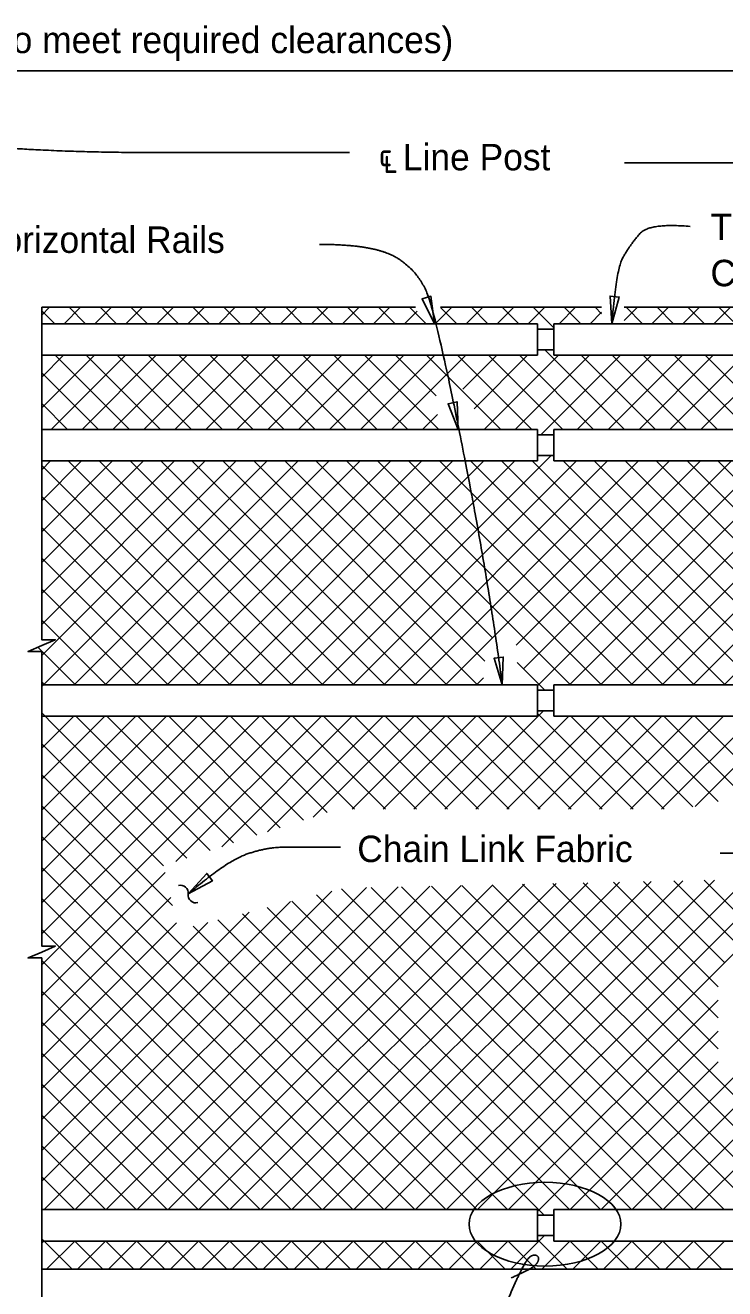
# Model space of a CAD drawing. Extents: x 110341.7 to 110413.5, y 110387.3 to 110417.8.
# Drawn here: x 110357.09 to 110362.42, y 110405.94 to 110415.57 of the extents above; entities that cross this region are included whole.
import ezdxf

# ---------------------------------------------------------------- set-up
doc = ezdxf.new("R2010")
doc.units = 0
for name, color, linetype in [('AdhocPoint_dp', 7, 'Continuous'), ('Border', 7, 'Continuous'), ('Patterning', 7, 'Continuous'), ('PlotBorder_dp', 7, 'Continuous'), ('SheetBorder_dp', 7, 'Continuous')]:
    doc.layers.add(name, color=color, linetype=linetype)

msp = doc.modelspace()

# ---------------------------------------------------------------- linework, layer by layer
at = {"layer": 'AdhocPoint_dp'}
for p, q in [((110360.9914, 110413.2966), (110357.2147, 110413.2966)), ((110360.9914, 110413.2966), (110360.9914, 110413.057)), ((110361.1164, 110413.255), (110360.9914, 110413.255)), ((110361.1164, 110413.2966), (110361.1164, 110413.057)), ((110365.0484, 110413.2966), (110361.1164, 110413.2966)), ((110360.9914, 110413.057), (110357.2147, 110413.057)), ((110361.1164, 110413.0987), (110360.9914, 110413.0987)), ((110365.0484, 110413.057), (110361.1164, 110413.057)), ((110360.9914, 110412.4912), (110357.2147, 110412.4912)), ((110360.9914, 110412.4912), (110360.9914, 110412.2516)), ((110365.0484, 110412.4912), (110361.1164, 110412.4912)), ((110361.1164, 110412.4911), (110361.1164, 110412.2516)), ((110361.1164, 110412.4495), (110360.9914, 110412.4495)), ((110361.1164, 110412.2933), (110360.9914, 110412.2933)), ((110360.9914, 110412.2516), (110357.2147, 110412.2516)), ((110365.0484, 110412.2516), (110361.1164, 110412.2516)), ((110360.9914, 110410.5466), (110357.2147, 110410.5466)), ((110360.9914, 110410.5466), (110360.9914, 110410.307)), ((110361.1164, 110410.5466), (110361.1164, 110410.307)), ((110365.0484, 110410.5466), (110361.1164, 110410.5466)), ((110361.1164, 110410.505), (110360.9914, 110410.505)), ((110360.9914, 110410.307), (110357.2147, 110410.307)), ((110361.1164, 110410.3487), (110360.9914, 110410.3487)), ((110365.0484, 110410.307), (110361.1164, 110410.307)), ((110360.9914, 110406.5466), (110357.2147, 110406.5466)), ((110360.9914, 110406.5466), (110360.9914, 110406.307)), ((110361.1164, 110406.5049), (110360.9914, 110406.5049)), ((110361.1164, 110406.5466), (110361.1164, 110406.307)), ((110365.0484, 110406.5466), (110361.1164, 110406.5466)), ((110360.9914, 110406.307), (110357.2147, 110406.307)), ((110361.1164, 110406.3487), (110360.9914, 110406.3487)), ((110365.0484, 110406.307), (110361.1164, 110406.307))]:
    msp.add_line(p, q, dxfattribs=at)
at = {"layer": 'Border'}
for points in [[(110354.5778, 110415.2246), (110356.0414, 110415.2246), (110356.0414, 110415.3279), (110356.0864, 110415.2246), (110356.1314, 110415.1213), (110356.1314, 110415.2246), (110367.5259, 110415.2246)], [(110357.2147, 110413.4227), (110357.2147, 110410.8892), (110357.3181, 110410.8892), (110357.2147, 110410.8442), (110357.1114, 110410.7992), (110357.2147, 110410.7992), (110357.2147, 110410.307)], [(110357.2147, 110410.307), (110357.2147, 110408.5545), (110357.3181, 110408.5545), (110357.2147, 110408.5095), (110357.1114, 110408.4645), (110357.2147, 110408.4645), (110357.2147, 110406.0934)], [(110357.2147, 110406.5102), (110357.2147, 110404.6594), (110357.3181, 110404.6594), (110357.2147, 110404.6144), (110357.1114, 110404.5694), (110357.2147, 110404.5694), (110357.2147, 110402.5685)]]:
    msp.add_lwpolyline(points, dxfattribs=at)
for points in [[(110360.2064, 110413.2966), (110360.1799, 110413.5062), (110360.1124, 110413.4858)], [(110361.5582, 110413.2967), (110361.6143, 110413.5003), (110361.5441, 110413.5074)], [(110360.3871, 110412.4911), (110360.3791, 110412.7022), (110360.3101, 110412.6878)], [(110360.7232, 110410.5466), (110360.7307, 110410.7577), (110360.6607, 110410.7484)], [(110358.3297, 110408.9521), (110358.5153, 110409.053), (110358.4717, 110409.1085)]]:
    msp.add_lwpolyline(points, close=True, dxfattribs=at)
for centre, start, end in [((110358.2713, 110408.9595), 352.34263, 104.06985), ((110358.3894, 110408.9436), 172.34263, 284.06985)]:
    msp.add_arc(centre, 0.0596, start, end, dxfattribs=at)
msp.add_ellipse((110361.0481, 110406.4357), major_axis=(-0.5785, 0), ratio=0.551825, dxfattribs=at)
for points in [[(110359.5594, 110414.6017), (110358.756, 110414.6017), (110357.3667, 110414.6017), (110356.1853, 110414.6963), (110355.5778, 110414.8004)], [(110361.6532, 110414.5236), (110362.0656, 110414.5236), (110363.8331, 110414.5236), (110365.0996, 110414.6466), (110365.5778, 110414.4473)], [(110362.1546, 110414.0385), (110361.8413, 110414.0669), (110361.6962, 110413.8967), (110361.5901, 110413.7126), (110361.5583, 110413.2966)], [(110359.3304, 110413.9019), (110359.7471, 110413.9019), (110360.0781, 110413.7056), (110360.2206, 110413.359), (110360.6083, 110411.4114), (110360.7232, 110410.5466)], [(110362.3836, 110409.2623), (110362.4628, 110409.2623), (110362.7363, 110409.2623), (110363.0431, 110409.3702), (110363.3333, 110409.6192)], [(110359.4911, 110409.3085), (110359.2009, 110409.3085), (110358.9273, 110409.3085), (110358.6206, 110409.2006), (110358.3304, 110408.9516)], [(110360.9877, 110405.649), (110360.7244, 110405.649), (110360.7442, 110405.8149), (110360.8614, 110406.0797), (110360.932, 110406.1998), (110360.999, 110406.1998), (110360.999, 110406.1433), (110360.9285, 110406.0868), (110360.7909, 110406.0268)]]:
    msp.add_open_spline(points, degree=2, dxfattribs=at)
at = {"layer": 'Patterning'}
for p, q in [((110357.2148, 110413.3624), (110357.2751, 110413.4227)), ((110357.2148, 110413.4227), (110360.0629, 110413.4227)), ((110357.2148, 110413.3957), (110357.3139, 110413.2966)), ((110357.3847, 110413.2966), (110357.5108, 110413.4227)), ((110357.4235, 110413.4227), (110357.5496, 110413.2966)), ((110357.6204, 110413.2966), (110357.7465, 110413.4227)), ((110357.6592, 110413.4227), (110357.7853, 110413.2966)), ((110357.8561, 110413.2966), (110357.9822, 110413.4227)), ((110357.8949, 110413.4227), (110358.021, 110413.2966)), ((110358.0918, 110413.2966), (110358.2179, 110413.4227)), ((110358.1306, 110413.4227), (110358.2567, 110413.2966)), ((110358.3275, 110413.2966), (110358.4536, 110413.4227)), ((110358.3663, 110413.4227), (110358.4924, 110413.2966)), ((110358.5632, 110413.2966), (110358.6893, 110413.4227)), ((110358.602, 110413.4227), (110358.7281, 110413.2966)), ((110358.7989, 110413.2966), (110358.925, 110413.4227)), ((110358.8377, 110413.4227), (110358.9638, 110413.2966)), ((110359.0346, 110413.2966), (110359.1607, 110413.4227)), ((110359.0734, 110413.4227), (110359.1995, 110413.2966)), ((110359.2703, 110413.2966), (110359.3964, 110413.4227)), ((110359.3091, 110413.4227), (110359.4352, 110413.2966)), ((110359.506, 110413.2966), (110359.6321, 110413.4227)), ((110359.5448, 110413.4227), (110359.6709, 110413.2966)), ((110359.7417, 110413.2966), (110359.8678, 110413.4227)), ((110359.7805, 110413.4227), (110359.9066, 110413.2966)), ((110359.9774, 110413.2966), (110360.0743, 110413.3935)), ((110360.0162, 110413.4227), (110360.1423, 110413.2966)), ((110360.2131, 110413.2966), (110360.3392, 110413.4227)), ((110360.2528, 110413.4227), (110361.4792, 110413.4227)), ((110360.2528, 110413.4218), (110360.378, 110413.2966)), ((110360.4488, 110413.2966), (110360.5749, 110413.4227)), ((110360.4876, 110413.4227), (110360.6137, 110413.2966)), ((110360.6845, 110413.2966), (110360.8106, 110413.4227)), ((110360.7233, 110413.4227), (110360.8494, 110413.2966)), ((110360.9202, 110413.2966), (110361.0463, 110413.4227)), ((110360.959, 110413.4227), (110361.1164, 110413.2654)), ((110361.1559, 110413.2966), (110361.282, 110413.4227)), ((110361.1947, 110413.4227), (110361.3208, 110413.2966)), ((110361.3916, 110413.2966), (110361.4792, 110413.3842)), ((110361.4304, 110413.4227), (110361.4792, 110413.3739)), ((110361.6525, 110413.3218), (110361.7534, 110413.4227)), ((110361.6525, 110413.4227), (110367.526, 110413.4227)), ((110361.6661, 110413.4227), (110361.7922, 110413.2966)), ((110361.863, 110413.2966), (110361.9891, 110413.4227)), ((110361.9018, 110413.4227), (110362.0279, 110413.2966)), ((110362.0987, 110413.2966), (110362.2248, 110413.4227)), ((110362.1376, 110413.4227), (110362.2636, 110413.2966)), ((110362.3345, 110413.2966), (110362.4605, 110413.4227)), ((110362.3733, 110413.4227), (110362.4993, 110413.2966)), ((110357.2148, 110412.6553), (110357.6165, 110413.057)), ((110357.2148, 110412.891), (110357.3808, 110413.057)), ((110357.2864, 110412.4912), (110357.8522, 110413.057)), ((110357.3177, 110413.057), (110357.8836, 110412.4912)), ((110357.5221, 110412.4912), (110358.0879, 110413.057)), ((110357.5534, 110413.057), (110358.1193, 110412.4912)), ((110357.7578, 110412.4912), (110358.3236, 110413.057)), ((110357.7891, 110413.057), (110358.355, 110412.4912)), ((110357.9935, 110412.4912), (110358.5593, 110413.057)), ((110358.0248, 110413.057), (110358.5907, 110412.4912)), ((110358.2292, 110412.4912), (110358.795, 110413.057)), ((110358.2605, 110413.057), (110358.8264, 110412.4912)), ((110358.4649, 110412.4912), (110359.0307, 110413.057)), ((110358.4962, 110413.057), (110359.0621, 110412.4912)), ((110358.7006, 110412.4912), (110359.2664, 110413.057)), ((110358.7319, 110413.057), (110359.2978, 110412.4912)), ((110358.9363, 110412.4912), (110359.5021, 110413.057)), ((110358.9677, 110413.057), (110359.5335, 110412.4912)), ((110359.172, 110412.4912), (110359.7378, 110413.057)), ((110359.2034, 110413.057), (110359.7692, 110412.4912)), ((110359.4077, 110412.4912), (110359.9735, 110413.057)), ((110359.4391, 110413.057), (110360.0049, 110412.4912)), ((110359.6434, 110412.4912), (110360.2093, 110413.057)), ((110359.6748, 110413.057), (110360.2406, 110412.4912)), ((110359.8791, 110412.4912), (110360.445, 110413.057)), ((110359.9105, 110413.057), (110360.22, 110412.7476)), ((110360.1462, 110413.057), (110360.712, 110412.4912)), ((110360.3819, 110413.057), (110360.9477, 110412.4912)), ((110360.4221, 110412.7985), (110360.6807, 110413.057)), ((110360.5083, 110412.649), (110360.9164, 110413.057)), ((110360.5862, 110412.4912), (110361.1521, 110413.057)), ((110360.6176, 110413.057), (110361.1834, 110412.4912)), ((110360.8219, 110412.4912), (110361.3878, 110413.057)), ((110360.8533, 110413.057), (110361.4191, 110412.4912)), ((110361.0159, 110412.4495), (110361.6235, 110413.057)), ((110361.0473, 110413.0987), (110361.6548, 110412.4912)), ((110361.2933, 110412.4912), (110361.8592, 110413.057)), ((110361.3247, 110413.057), (110361.8905, 110412.4912)), ((110361.529, 110412.4912), (110362.0949, 110413.057)), ((110361.5604, 110413.057), (110362.1262, 110412.4912)), ((110361.7647, 110412.4912), (110362.3306, 110413.057)), ((110361.7961, 110413.057), (110362.362, 110412.4912)), ((110362.0004, 110412.4912), (110362.5663, 110413.057)), ((110362.0318, 110413.057), (110362.5977, 110412.4912)), ((110362.2361, 110412.4912), (110362.802, 110413.057)), ((110362.2675, 110413.057), (110362.8334, 110412.4912)), ((110357.2148, 110412.9243), (110357.6479, 110412.4912)), ((110357.2148, 110412.6886), (110357.4122, 110412.4912)), ((110360.1148, 110412.4912), (110360.2296, 110412.606)), ((110359.3487, 110410.5466), (110361.0954, 110412.2933)), ((110357.2148, 110410.7697), (110358.6967, 110412.2516)), ((110357.2148, 110410.534), (110358.9324, 110412.2516)), ((110357.2148, 110411.0054), (110358.461, 110412.2516)), ((110357.2148, 110411.2411), (110358.2253, 110412.2516)), ((110357.2148, 110411.4768), (110357.9896, 110412.2516)), ((110357.2148, 110411.7125), (110357.7539, 110412.2516)), ((110357.2148, 110412.1839), (110357.2825, 110412.2516)), ((110357.2148, 110411.9482), (110357.5182, 110412.2516)), ((110357.2148, 110412.2172), (110358.8853, 110410.5466)), ((110357.4161, 110412.2516), (110359.121, 110410.5466)), ((110357.4631, 110410.5466), (110359.1681, 110412.2516)), ((110357.6518, 110412.2516), (110359.3567, 110410.5466)), ((110357.6988, 110410.5466), (110359.4038, 110412.2516)), ((110357.8875, 110412.2516), (110359.5925, 110410.5466)), ((110357.9345, 110410.5466), (110359.6395, 110412.2516)), ((110358.1232, 110412.2516), (110359.8282, 110410.5466)), ((110358.1702, 110410.5466), (110359.8752, 110412.2516)), ((110358.3589, 110412.2516), (110360.0639, 110410.5466)), ((110358.4059, 110410.5466), (110360.1109, 110412.2516)), ((110358.5946, 110412.2516), (110360.2996, 110410.5466)), ((110358.6416, 110410.5466), (110360.3466, 110412.2516)), ((110358.8303, 110412.2516), (110360.5353, 110410.5466)), ((110358.8773, 110410.5466), (110360.5823, 110412.2516)), ((110359.066, 110412.2516), (110360.5912, 110410.7263)), ((110359.113, 110410.5466), (110360.818, 110412.2516)), ((110359.3017, 110412.2516), (110360.6458, 110410.9075)), ((110359.5374, 110412.2516), (110361.2424, 110410.5466)), ((110359.5845, 110410.5466), (110361.2894, 110412.2516)), ((110359.7731, 110412.2516), (110361.4781, 110410.5466)), ((110359.8202, 110410.5466), (110361.5251, 110412.2516)), ((110360.0088, 110412.2516), (110361.7138, 110410.5466)), ((110360.0559, 110410.5466), (110361.7608, 110412.2516)), ((110360.2445, 110412.2516), (110361.9495, 110410.5466)), ((110360.2916, 110410.5466), (110361.9965, 110412.2516)), ((110360.4802, 110412.2516), (110362.1852, 110410.5466)), ((110360.7159, 110412.2516), (110362.4209, 110410.5466)), ((110360.8283, 110410.8477), (110362.2322, 110412.2516)), ((110360.8848, 110410.6685), (110362.4679, 110412.2516)), ((110360.9516, 110412.2516), (110362.6566, 110410.5466)), ((110360.9914, 110410.5393), (110362.7036, 110412.2516)), ((110361.1873, 110412.2516), (110362.8923, 110410.5466)), ((110361.2344, 110410.5466), (110362.9393, 110412.2516)), ((110361.423, 110412.2516), (110363.128, 110410.5466)), ((110361.4701, 110410.5466), (110363.175, 110412.2516)), ((110361.6587, 110412.2516), (110363.3637, 110410.5466)), ((110361.7058, 110410.5466), (110363.4107, 110412.2516)), ((110361.8944, 110412.2516), (110363.5994, 110410.5466)), ((110361.9415, 110410.5466), (110363.6464, 110412.2516)), ((110362.1301, 110412.2516), (110363.8351, 110410.5466)), ((110362.1772, 110410.5466), (110363.8821, 110412.2516)), ((110362.3658, 110412.2516), (110364.0708, 110410.5466)), ((110362.4129, 110410.5466), (110364.1178, 110412.2516)), ((110357.2148, 110411.9815), (110358.6496, 110410.5466)), ((110357.2148, 110411.7458), (110358.4139, 110410.5466)), ((110357.2148, 110411.5101), (110358.1782, 110410.5466)), ((110357.2148, 110411.2744), (110357.9425, 110410.5466)), ((110357.2148, 110411.0387), (110357.7068, 110410.5466)), ((110357.186, 110410.8317), (110357.4711, 110410.5466)), ((110360.8363, 110410.717), (110361.0483, 110410.505)), ((110357.2148, 110410.5673), (110357.2354, 110410.5466)), ((110360.5273, 110410.5466), (110360.5797, 110410.5991)), ((110357.2148, 110410.3316), (110357.3134, 110410.2329)), ((110357.2148, 110408.4126), (110359.1092, 110410.307)), ((110357.2148, 110408.6483), (110358.8735, 110410.307)), ((110357.2148, 110409.1197), (110358.4021, 110410.307)), ((110357.2148, 110409.3554), (110358.1664, 110410.307)), ((110357.2148, 110409.8269), (110357.695, 110410.307)), ((110357.2148, 110409.5911), (110357.9307, 110410.307)), ((110357.2148, 110410.0626), (110357.4593, 110410.307)), ((110357.2148, 110410.2983), (110357.2235, 110410.307)), ((110357.2186, 110408.8879), (110358.6378, 110410.307)), ((110357.475, 110410.307), (110358.4983, 110409.2838)), ((110357.7107, 110410.307), (110358.6762, 110409.3415)), ((110357.9464, 110410.307), (110358.8542, 110409.3993)), ((110358.1821, 110410.307), (110359.0322, 110409.457)), ((110358.2368, 110409.199), (110359.3449, 110410.307)), ((110358.328, 110410.2329), (110358.4021, 110410.307)), ((110358.4178, 110410.307), (110359.2101, 110409.5147)), ((110358.5857, 110409.3122), (110359.5806, 110410.307)), ((110358.6535, 110410.307), (110359.3881, 110409.5725)), ((110358.8892, 110410.307), (110359.5981, 110409.5981)), ((110358.9346, 110409.4253), (110359.8163, 110410.307)), ((110359.1249, 110410.307), (110359.8338, 110409.5981)), ((110359.2834, 110409.5385), (110360.052, 110410.307)), ((110359.3606, 110410.307), (110360.0695, 110409.5981)), ((110359.5788, 110409.5981), (110360.2877, 110410.307)), ((110359.5963, 110410.307), (110360.3052, 110409.5981)), ((110359.8145, 110409.5981), (110360.5234, 110410.307)), ((110359.832, 110410.307), (110360.5409, 110409.5981)), ((110360.0502, 110409.5981), (110360.7591, 110410.307)), ((110360.0677, 110410.307), (110360.7766, 110409.5981)), ((110360.2859, 110409.5981), (110361.0365, 110410.3487)), ((110360.3034, 110410.307), (110361.0123, 110409.5981)), ((110360.5216, 110409.5981), (110361.2305, 110410.307)), ((110360.5391, 110410.307), (110361.248, 110409.5981)), ((110360.7573, 110409.5981), (110361.4662, 110410.307)), ((110360.7748, 110410.307), (110361.4837, 110409.5981)), ((110360.9914, 110410.3262), (110361.7194, 110409.5981)), ((110360.993, 110409.5981), (110361.7019, 110410.307)), ((110361.2287, 110409.5981), (110361.9376, 110410.307)), ((110361.2462, 110410.307), (110361.9552, 110409.5981)), ((110361.4644, 110409.5981), (110362.1733, 110410.307)), ((110361.4819, 110410.307), (110362.1735, 110409.6155)), ((110361.7001, 110409.5981), (110362.409, 110410.307)), ((110361.7177, 110410.307), (110362.368, 110409.6567)), ((110361.9358, 110409.5981), (110362.6447, 110410.307)), ((110361.9534, 110410.307), (110362.5625, 110409.6979)), ((110362.1891, 110410.307), (110362.7571, 110409.739)), ((110362.1929, 110409.6196), (110362.8804, 110410.307)), ((110357.3134, 110410.2329), (110358.3203, 110409.2261)), ((110357.2148, 110410.0959), (110358.143, 110409.1677)), ((110357.2148, 110409.8602), (110358.2113, 110408.8636)), ((110357.2148, 110409.6245), (110360.2926, 110406.5466)), ((110357.2148, 110409.3888), (110360.0569, 110406.5466)), ((110360.5342, 110406.5466), (110363.2565, 110409.269)), ((110357.2148, 110409.1531), (110359.8212, 110406.5466)), ((110357.2148, 110408.1769), (110358.1545, 110409.1166)), ((110357.47, 110406.5466), (110359.9291, 110409.0057)), ((110357.7057, 110406.5466), (110360.1701, 110409.0109)), ((110357.9415, 110406.5466), (110360.411, 110409.0162)), ((110358.1772, 110406.5466), (110360.652, 110409.0214)), ((110358.4129, 110406.5466), (110360.893, 110409.0267)), ((110358.6486, 110406.5466), (110361.1339, 110409.032)), ((110358.8843, 110406.5466), (110361.3749, 110409.0372)), ((110359.12, 110406.5466), (110361.6159, 110409.0425)), ((110359.3557, 110406.5466), (110361.8568, 110409.0478)), ((110359.5914, 110406.5466), (110362.0978, 110409.053)), ((110359.8271, 110406.5466), (110362.3387, 110409.0583)), ((110359.9544, 110409.0062), (110362.414, 110406.5466)), ((110360.0628, 110406.5466), (110362.5797, 110409.0635)), ((110360.185, 110409.0112), (110362.6497, 110406.5466)), ((110360.2985, 110406.5466), (110362.8207, 110409.0688)), ((110360.4157, 110409.0163), (110362.8854, 110406.5466)), ((110360.6464, 110409.0213), (110363.1211, 110406.5466)), ((110360.877, 110409.0264), (110363.3568, 110406.5466)), ((110361.1077, 110409.0314), (110362.3667, 110407.7724)), ((110361.3383, 110409.0364), (110362.3667, 110408.0081)), ((110361.569, 110409.0415), (110362.3667, 110408.2438)), ((110361.7997, 110409.0465), (110362.4169, 110408.4293)), ((110362.0303, 110409.0515), (110362.6104, 110408.4715)), ((110362.261, 110409.0566), (110362.8461, 110408.4715)), ((110357.2147, 110406.7627), (110359.4258, 110408.9738)), ((110357.2148, 110407.9412), (110358.1977, 110408.9242)), ((110357.2148, 110408.9174), (110359.5855, 110406.5466)), ((110357.2343, 110406.5466), (110359.6881, 110409.0004)), ((110359.3092, 110408.9443), (110361.7069, 110406.5466)), ((110359.4973, 110408.9918), (110361.9426, 110406.5466)), ((110359.7237, 110409.0012), (110362.1783, 110406.5466)), ((110357.2147, 110406.9984), (110359.1104, 110408.8941)), ((110357.2148, 110407.2341), (110358.795, 110408.8144)), ((110358.9328, 110408.8492), (110361.2355, 110406.5466)), ((110359.121, 110408.8968), (110361.4712, 110406.5466)), ((110357.2148, 110407.4698), (110358.4796, 110408.7347)), ((110357.2148, 110407.7055), (110358.241, 110408.7318)), ((110358.5565, 110408.7541), (110360.764, 110406.5466)), ((110358.7447, 110408.8017), (110361.0414, 110406.5049)), ((110357.2148, 110408.6817), (110359.3498, 110406.5466)), ((110358.3684, 110408.7066), (110360.5283, 110406.5466)), ((110357.2148, 110408.446), (110359.1141, 110406.5466)), ((110357.2148, 110408.2103), (110358.8784, 110406.5466)), ((110360.7699, 110406.5466), (110362.3667, 110408.1434)), ((110357.2148, 110407.9746), (110358.6427, 110406.5466)), ((110360.9914, 110406.5324), (110362.3667, 110407.9077)), ((110357.2148, 110407.7389), (110358.407, 110406.5466)), ((110361.2413, 110406.5466), (110362.3667, 110407.672)), ((110361.477, 110406.5466), (110362.5749, 110407.6446)), ((110361.7127, 110406.5466), (110362.8106, 110407.6446)), ((110361.9484, 110406.5466), (110363.0463, 110407.6446)), ((110362.1841, 110406.5466), (110363.282, 110407.6446)), ((110357.2148, 110407.5032), (110358.1713, 110406.5466)), ((110357.2148, 110407.2675), (110357.9356, 110406.5466)), ((110357.2147, 110407.0318), (110357.6999, 110406.5466)), ((110357.2147, 110406.7961), (110357.4642, 110406.5466)), ((110357.2147, 110406.3247), (110357.446, 110406.0935)), ((110357.2147, 110406.2913), (110357.2305, 110406.307)), ((110357.2526, 110406.0935), (110357.4662, 110406.307)), ((110357.4681, 110406.307), (110357.6817, 110406.0935)), ((110357.4883, 110406.0935), (110357.7019, 110406.307)), ((110357.7038, 110406.307), (110357.9174, 110406.0935)), ((110357.724, 110406.0935), (110357.9376, 110406.307)), ((110357.9395, 110406.307), (110358.1531, 110406.0935)), ((110357.9597, 110406.0935), (110358.1733, 110406.307)), ((110358.1752, 110406.307), (110358.3888, 110406.0935)), ((110358.1954, 110406.0935), (110358.409, 110406.307)), ((110358.4109, 110406.307), (110358.6245, 110406.0935)), ((110358.4311, 110406.0935), (110358.6447, 110406.307)), ((110358.6466, 110406.307), (110358.8602, 110406.0935)), ((110358.6668, 110406.0935), (110358.8804, 110406.307)), ((110358.8823, 110406.307), (110359.0959, 110406.0935)), ((110358.9025, 110406.0935), (110359.1161, 110406.307)), ((110359.118, 110406.307), (110359.3316, 110406.0935)), ((110359.1382, 110406.0935), (110359.3518, 110406.307)), ((110359.3537, 110406.307), (110359.5673, 110406.0935)), ((110359.3739, 110406.0935), (110359.5875, 110406.307)), ((110359.5894, 110406.307), (110359.803, 110406.0935)), ((110359.6096, 110406.0935), (110359.8232, 110406.307)), ((110359.8251, 110406.307), (110360.0387, 110406.0935)), ((110359.8453, 110406.0935), (110360.0589, 110406.307)), ((110360.0608, 110406.307), (110360.2744, 110406.0935)), ((110360.081, 110406.0935), (110360.2946, 110406.307)), ((110360.2965, 110406.307), (110360.5101, 110406.0935)), ((110360.3167, 110406.0935), (110360.5303, 110406.307)), ((110360.5322, 110406.307), (110360.7458, 110406.0935)), ((110360.5524, 110406.0935), (110360.766, 110406.307)), ((110360.7679, 110406.307), (110360.9815, 110406.0935)), ((110360.7881, 110406.0935), (110361.0434, 110406.3487)), ((110360.9914, 110406.3193), (110361.2172, 110406.0935)), ((110361.0238, 110406.0935), (110361.2374, 110406.307)), ((110361.2393, 110406.307), (110361.4529, 110406.0935)), ((110361.2595, 110406.0935), (110361.4731, 110406.307)), ((110361.475, 110406.307), (110361.6886, 110406.0935)), ((110361.4952, 110406.0935), (110361.7088, 110406.307)), ((110361.7107, 110406.307), (110361.9243, 110406.0935)), ((110361.7309, 110406.0935), (110361.9445, 110406.307)), ((110361.9464, 110406.307), (110362.16, 110406.0935)), ((110361.9667, 110406.0935), (110362.1802, 110406.307)), ((110362.1821, 110406.307), (110362.3957, 110406.0935)), ((110362.2024, 110406.0935), (110362.4159, 110406.307))]:
    msp.add_line(p, q, dxfattribs=at)
at = {"layer": 'PlotBorder_dp'}
msp.add_line((110357.2147, 110406.0935), (110364.5166, 110406.0935), dxfattribs=at)

# ---------------------------------------------------------------- texts
at = {"layer": 'Border'}
for s, p in [('Ties @ 2\'-0" ', (110362.3089, 110413.9348)), ('Centers (Typ.)', (110362.3089, 110413.5828))]:
    msp.add_text(s, height=0.2016, dxfattribs=at).set_placement(p)
at = {"layer": 'SheetBorder_dp'}
for s, p in [('Equal Spaces @ 10\'-0" Max. (Posts may be shifted minimally to meet required clearances)', (110349.5454, 110415.3593)), ('℄ Line Post', (110359.7815, 110414.4661)), ('Horizontal Rails', (110356.7217, 110413.837)), ('Chain Link Fabric', (110359.6183, 110409.1949))]:
    msp.add_text(s, height=0.2016, dxfattribs=at).set_placement(p)

doc.saveas('drawing.dxf')
